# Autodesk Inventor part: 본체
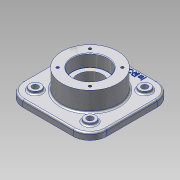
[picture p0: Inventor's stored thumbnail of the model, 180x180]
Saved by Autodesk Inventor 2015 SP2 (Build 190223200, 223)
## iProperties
Created: 2015-07
Part Number: 본체
Material: 알루미늄 6061
Document SubType Name: Modeling
Designer: AMC
Density: 2.7 g/cm^3
Appearance: 알루미늄 - 평지
Mass: 1459.27 g
Surface Area: 800.934 cm^2
Volume: 540.471 cm^3
Author: AMC
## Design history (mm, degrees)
sketch "스케치1"
  geometry: L1 (-75, -75)-(75, -75); L2 (75, -75)-(75, 75); L3 (75, 75)-(-75, 75); L4 (-75, 75)-(-75, -75); L5 (-75, -75)-(75, 75); L6 (75, -75)-(-75, 75); 1 further point
  constraints: 12 end point, 2 midpoint, 2 parallel, 1 horizontal, 1 perpendicular
  dimensions: "d0" = 150 distance of L3.end L2.end; "d1" = 150 distance of L2.end L1.end
extrude "돌출1" new body sketch "스케치1" distance "d2" = 12; taper "d3" = 0 deg
sketch "스케치2"
  geometry: C1 r 50 at (0, 0); 1 further point
  constraints: 1 centre point, 1 coincident
  dimensions: "d4" = 100 diameter of C1
extrude "돌출2" join sketch "스케치2" distance "d5" = 47; taper "d7" = 0 deg; dims "d6" = 23, "d8" = 0
hole "구멍1" diameter "d11" = 45; stored, may be unused: countersink angle "d15" = 90 deg, drill point angle "d17" = 0 deg; dims "d9" = 10, "d10" = 10, "d12" = 6, "d13" = 62, "d14" = 22, "d16" = 48
hole "구멍2" diameter "d20" = 62; stored, may be unused: countersink angle "d24" = 90 deg, drill point angle "d26" = 0 deg; dims "d18" = 10, "d19" = 10, "d21" = 6, "d22" = 62, "d23" = 22, "d25" = 22
sketch "스케치3"
  geometry: C1 r 10 at (-49, 49); C2 r 10 at (49, 49); C3 r 10 at (-49, -49); C4 r 10 at (49, -49); 1 further point
  constraints: 4 centre point, 2 horizontal alignment
  dimensions: "d27" = 20 diameter of C1; "d28" = 20 diameter of C2; "d29" = 20 diameter of C3; "d30" = 20 diameter of C4; "d31" = 49 horizontal distance of C1.centre point (0, 0); "d32" = 49 horizontal distance of C2.centre point (0, 0); "d33" = 49 horizontal distance of C3.centre point (0, 0); "d34" = 49 horizontal distance of point (0, 0) C4.centre; "d35" = 49 horizontal distance of C2.centre point (0, 0); "d36" = 49 horizontal distance of C4.centre point (0, 0)
extrude "돌출3" join sketch "스케치3" distance "d37" = 5; taper "d38" = 0 deg
fillet "모깎기1" dims "d39" = 30
sketch "스케치4"
  geometry: L1 (0, 0)-(41, 0); L2 (0, 0)-(28.991, 28.991); A1 r 41 centre (0, 0) between (41, 0) and (28.991, 28.991); 2 further points
  constraints: 4 end point, 2 coincident, 2 point on circle, 1 centre point, 1 horizontal
  dimensions: "d40" = 82 diameter of A1; "d41" = 45 deg angle of L1 L2
hole "구멍3" sketch "스케치4" at (28.991, 28.991) diameter "d42" = 4.917; stored, may be unused: countersink angle "d46" = 90 deg, drill point angle "d48" = 118 deg; dims "d43" = 10, "d44" = 62, "d45" = 22, "d47" = 13
sketch "스케치5"
  geometry: L1 (0, 0)-(41, 0); L2 (0, 0)-(28.991, 28.991); A1 r 41 centre (0, 0) between (41, 0) and (28.991, 28.991); 2 further points
  constraints: 4 end point, 2 coincident, 2 point on circle, 1 centre point, 1 horizontal
  dimensions: "d52" = 82 diameter of A1; "d53" = 45 deg angle of L1 L2
hole "구멍4" sketch "스케치5" at (28.991, 28.991) diameter "d54" = 4.917; stored, may be unused: countersink angle "d58" = 90 deg, drill point angle "d60" = 118 deg; dims "d55" = 10, "d56" = 62, "d57" = 22, "d59" = 13
hole "구멍5" diameter "d66" = 11; stored, may be unused: countersink angle "d70" = 90 deg, drill point angle "d72" = 0 deg; dims "d64" = 10, "d65" = 10, "d67" = 10, "d68" = 62, "d69" = 22, "d71" = 13
hole "구멍6" diameter "d75" = 11; stored, may be unused: countersink angle "d79" = 90 deg, drill point angle "d81" = 0 deg; dims "d73" = 10, "d74" = 10, "d76" = 10, "d77" = 62, "d78" = 22, "d80" = 13
hole "구멍7" diameter "d84" = 11; stored, may be unused: countersink angle "d88" = 90 deg, drill point angle "d90" = 0 deg; dims "d82" = 10, "d83" = 10, "d85" = 10, "d86" = 62, "d87" = 22, "d89" = 13
hole "구멍8" diameter "d93" = 11; stored, may be unused: countersink angle "d97" = 90 deg, drill point angle "d99" = 0 deg; dims "d91" = 10, "d92" = 10, "d94" = 10, "d95" = 62, "d96" = 22, "d98" = 13
chamfer "모따기1" distance "d100" = 1; stored, may be unused: second distance "d101" = 2, angle "d102" = 45 deg
fillet "모깎기2" dims "d103" = 3
fillet "모깎기3" dims "d104" = 3
fillet "모깎기4" dims "d105" = 3
fillet "모깎기5" dims "d106" = 0.3
sketch "스케치6"
  geometry: 2 further points
  constraints: 1 vertical alignment, 1 other
  dimensions: "d107" = 65 distance of point (0, 0) point (0, 65)
feature "엠보싱1" sketch "스케치6" dims "d0" = 150, "d1" = 150, "d108" = 1, "d109" = 0
node "솔리드1"
pattern_circular "원형 패턴1" dims angle "d50" = 360 deg
pattern_circular "원형 패턴2" dims angle "d62" = 360 deg
